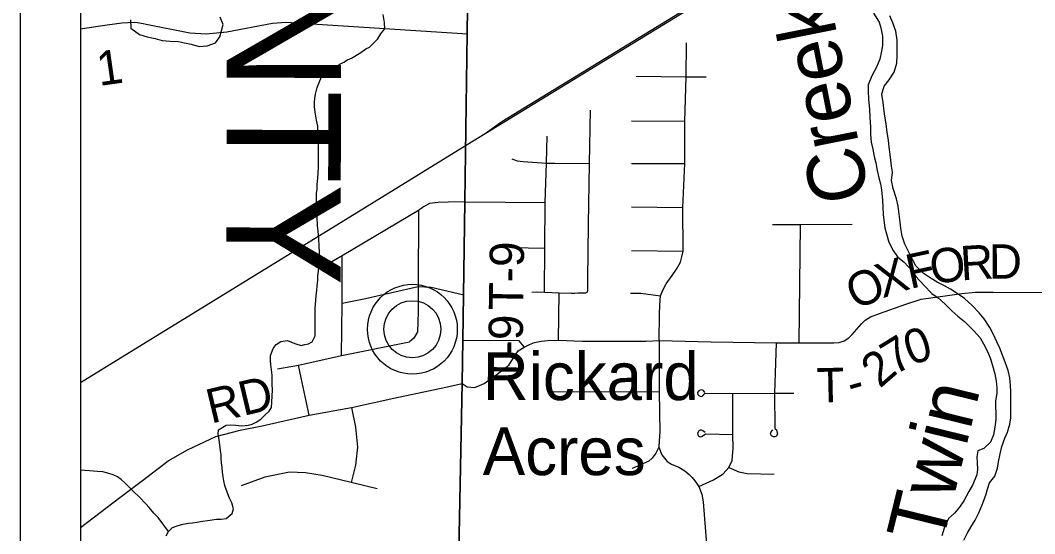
# Model space of a CAD drawing. Extents: x -7.3 to 34, y 0 to 22.
# Drawn here: x 2 to 3.68, y 17.363 to 18.213 of the extents above; entities that cross this region are included whole.
import ezdxf

# ---------------------------------------------------------------- set-up
doc = ezdxf.new("R2010")
doc.units = 0
for name, color, linetype in [('GM_X_Corporation', 7, 'Continuous'), ('GM_X_County_Road', 7, 'Continuous'), ('GM_X_County_Road_Text', 7, 'Continuous'), ('GM_X_County_Text', 7, 'Continuous'), ('GM_X_Major_River', 7, 'Continuous'), ('GM_X_Major_River_Text', 7, 'Continuous'), ('GM_X_Minor_River', 7, 'Continuous'), ('GM_X_Rail_Line', 7, 'Continuous'), ('GM_X_Township_Road', 7, 'Continuous'), ('GM_X_Township_Road_Text', 7, 'Continuous'), ('GM_X_Unincorporated', 7, 'Continuous'), ('GM_X_Unincorporated_Location', 7, 'Continuous'), ('GM_X_Unincorporated_Text', 7, 'Continuous'), ('SH_Data', 7, 'Continuous')]:
    doc.layers.add(name, color=color, linetype=linetype)

msp = doc.modelspace()

# ---------------------------------------------------------------- linework, layer by layer
at = {"layer": 'GM_X_Corporation'}
for points in [[(2.1, 20.0921), (2.1, 14.1)], [(2.1, 20.0921), (2.1, 17.0429)], [(2.7253, 17.2786), (2.7319, 17.6124), (2.7331, 17.6845), (2.7344, 17.7586), (2.7366, 17.9136), (2.7405, 18.1914), (2.7466, 18.6965), (2.7401, 19.6966), (2.7402, 19.7107)], [(2.7402, 19.7107), (2.7401, 19.6966), (2.7466, 18.6965), (2.7405, 18.1914), (2.7366, 17.9136), (2.7344, 17.7586), (2.7331, 17.6845), (2.7319, 17.6124), (2.7253, 17.2786)], [(2.7253, 17.2786), (2.7319, 17.6124), (2.7331, 17.6845), (2.7344, 17.7586), (2.7366, 17.9136), (2.7405, 18.1914), (2.7466, 18.6965), (2.7401, 19.6966), (2.7402, 19.7107)], [(2.7402, 19.7107), (2.7401, 19.6966), (2.7466, 18.6965), (2.7405, 18.1914), (2.7366, 17.9136), (2.7344, 17.7586), (2.7331, 17.6845), (2.7319, 17.6124), (2.7253, 17.2786)]]:
    msp.add_lwpolyline(points, dxfattribs=at)
at = {"layer": 'GM_X_County_Road'}
msp.add_lwpolyline([(2.1, 17.3735), (2.1648, 17.4235), (2.2023, 17.4517), (2.2448, 17.4839), (2.2768, 17.502), (2.324, 17.5245), (2.3644, 17.5348), (2.4007, 17.5419), (2.4787, 17.5598), (2.5485, 17.5723), (2.6188, 17.5877), (2.7048, 17.6058), (2.7321, 17.6118)], dxfattribs=at)
at = {"layer": 'GM_X_Major_River'}
for points in [[(3.4134, 18.2251), (3.4229, 18.2104), (3.4257, 18.2009), (3.4284, 18.1871), (3.4283, 18.1719), (3.4266, 18.1621), (3.4236, 18.1492), (3.4183, 18.1361), (3.4107, 18.1214), (3.4046, 18.1064), (3.4044, 18.0969), (3.4052, 18.0824), (3.4066, 18.0664), (3.4074, 18.0527), (3.4081, 18.0364), (3.4086, 18.0242), (3.4094, 18.0116), (3.4121, 18.0002), (3.4145, 17.9879), (3.4172, 17.9776), (3.4195, 17.9646), (3.4223, 17.9528), (3.4247, 17.9428), (3.4263, 17.9325), (3.4281, 17.9158), (3.429, 17.904), (3.4294, 17.8918), (3.4303, 17.8823), (3.4322, 17.87), (3.4346, 17.8601), (3.4388, 17.8459), (3.446, 17.8321), (3.453, 17.822), (3.4649, 17.8122), (3.4767, 17.7994), (3.4836, 17.7893)], [(3.4653, 17.843), (3.4607, 17.856), (3.4584, 17.8694), (3.4575, 17.8793), (3.456, 17.8926), (3.454, 17.9056), (3.4513, 17.9178), (3.4461, 17.9351), (3.443, 17.9484), (3.4449, 17.9621), (3.4432, 17.972), (3.442, 17.9819), (3.4407, 17.9915), (3.4395, 18.0033), (3.4379, 18.0151), (3.436, 18.0277), (3.4344, 18.0418), (3.4321, 18.0548), (3.4305, 18.0673), (3.4293, 18.0776), (3.427, 18.091), (3.4308, 18.1046), (3.4394, 18.115), (3.4477, 18.1277), (3.4518, 18.1424), (3.4525, 18.155), (3.4524, 18.1652), (3.4524, 18.1804), (3.4502, 18.1953), (3.4452, 18.2095), (3.4406, 18.221)], [(3.5629, 17.3527), (3.5685, 17.3636), (3.5748, 17.3744), (3.5816, 17.386), (3.588, 17.398), (3.5932, 17.4112), (3.5993, 17.4274), (3.6022, 17.4372), (3.6056, 17.4477), (3.6142, 17.4589), (3.6187, 17.4717), (3.6205, 17.4823), (3.6231, 17.4955), (3.6257, 17.5076), (3.631, 17.5215), (3.635, 17.5313), (3.6392, 17.5445), (3.6406, 17.5555), (3.6409, 17.5692), (3.6409, 17.5836), (3.6406, 17.5977), (3.6405, 17.6095), (3.6389, 17.6217), (3.6362, 17.6335), (3.6312, 17.6473), (3.627, 17.6592), (3.6224, 17.6707), (3.6177, 17.6811), (3.6123, 17.6934), (3.6062, 17.7046), (3.5967, 17.7192), (3.5886, 17.7289), (3.5768, 17.741), (3.5638, 17.7527), (3.5534, 17.7598), (3.5407, 17.7681), (3.531, 17.7737), (3.519, 17.7797), (3.5089, 17.786), (3.4955, 17.7947), (3.4833, 17.8068), (3.4779, 17.8172), (3.4729, 17.8276), (3.4653, 17.843)], [(3.4836, 17.7893), (3.4973, 17.7742), (3.5102, 17.7613), (3.5202, 17.7538), (3.5321, 17.7437), (3.5428, 17.7324), (3.5528, 17.7234), (3.564, 17.7147), (3.5787, 17.6999), (3.5898, 17.6875), (3.5956, 17.6775), (3.6021, 17.6651), (3.6064, 17.6544), (3.6102, 17.6421), (3.6144, 17.6283), (3.6164, 17.6161), (3.6176, 17.6051), (3.6177, 17.5956), (3.6152, 17.5835), (3.6153, 17.5732), (3.6158, 17.563), (3.6159, 17.5527), (3.6144, 17.5398), (3.6118, 17.5273), (3.6073, 17.5149), (3.596, 17.5046), (3.5861, 17.5006), (3.5843, 17.4904), (3.5848, 17.4805), (3.5853, 17.4703), (3.5847, 17.4608), (3.5774, 17.4435), (3.571, 17.433), (3.5631, 17.418), (3.556, 17.4072), (3.5477, 17.3975), (3.5376, 17.3883), (3.5304, 17.3725), (3.5267, 17.3597)]]:
    msp.add_lwpolyline(points, dxfattribs=at)
at = {"layer": 'GM_X_Minor_River'}
for points in [[(2.1825, 18.2144), (2.1829, 18.2003), (2.1975, 18.1898), (2.2103, 18.1861), (2.2236, 18.1835), (2.2349, 18.1802), (2.2481, 18.1788), (2.2618, 18.1786), (2.272, 18.1764), (2.2833, 18.1739), (2.2965, 18.1702), (2.3098, 18.1711), (2.3232, 18.1762), (2.3306, 18.1863), (2.3331, 18.1961), (2.336, 18.2063), (2.3313, 18.2186)], [(2.4909, 17.9019), (2.4906, 17.9156), (2.4907, 17.927), (2.4915, 17.9335), (2.4919, 17.9418), (2.4931, 17.952), (2.494, 17.9691), (2.4937, 17.9828), (2.4942, 18.0044), (2.4943, 18.0124), (2.4929, 18.0314), (2.4926, 18.0379), (2.4908, 18.0481), (2.4882, 18.0614), (2.4875, 18.0709), (2.4876, 18.0778), (2.488, 18.0842), (2.4892, 18.091), (2.4919, 18.1024), (2.495, 18.1107), (2.4992, 18.1198), (2.5034, 18.1258), (2.5145, 18.1326), (2.522, 18.1371), (2.5361, 18.1442), (2.5422, 18.1479), (2.5486, 18.1509), (2.5642, 18.1602), (2.5726, 18.1662), (2.5786, 18.1692), (2.5916, 18.1824), (2.5985, 18.1929), (2.6038, 18.1993), (2.6035, 18.2096), (2.6013, 18.2229)], [(2.2419, 17.36), (2.2453, 17.3671), (2.2522, 17.3735), (2.2598, 17.3765), (2.2693, 17.3794), (2.2787, 17.3809), (2.2855, 17.3816), (2.2923, 17.3826), (2.3018, 17.3841), (2.3101, 17.3855), (2.3177, 17.3866), (2.3249, 17.3873), (2.3325, 17.3876), (2.3412, 17.3886), (2.3511, 17.3969), (2.353, 17.4048), (2.3504, 17.4144), (2.3467, 17.422), (2.3437, 17.4296), (2.3411, 17.4368), (2.3389, 17.4433), (2.3371, 17.4509), (2.336, 17.4577), (2.3349, 17.4654), (2.3342, 17.4733), (2.3335, 17.4809), (2.3328, 17.4881), (2.3325, 17.4946), (2.3318, 17.5007), (2.3307, 17.5106), (2.3293, 17.5189), (2.3278, 17.5284), (2.3286, 17.5352), (2.3408, 17.5431), (2.3484, 17.5438), (2.357, 17.5433), (2.3669, 17.5421), (2.3775, 17.5431), (2.3843, 17.5446), (2.3907, 17.548), (2.3983, 17.5528), (2.4056, 17.56), (2.412, 17.566), (2.4159, 17.5724), (2.4167, 17.5811), (2.4176, 17.6016), (2.4173, 17.6111), (2.4173, 17.6191), (2.417, 17.6259), (2.4149, 17.6438), (2.4142, 17.6498), (2.4142, 17.6586), (2.4188, 17.6703), (2.4238, 17.6767), (2.4318, 17.6816), (2.4424, 17.6834), (2.4492, 17.6803), (2.4567, 17.6775), (2.465, 17.6752), (2.4715, 17.6766), (2.4775, 17.6777), (2.4836, 17.6811), (2.4882, 17.6909), (2.4883, 17.6996), (2.4887, 17.7061), (2.4884, 17.7175), (2.4885, 17.7365), (2.489, 17.7433), (2.4894, 17.7494), (2.4902, 17.7577), (2.491, 17.766), (2.4918, 17.774), (2.4926, 17.7831), (2.4931, 17.7899), (2.4939, 17.7979), (2.4947, 17.8043), (2.4955, 17.8172), (2.4956, 17.8302), (2.4953, 17.8396), (2.4943, 17.8518), (2.4936, 17.8643), (2.4925, 17.8735), (2.4915, 17.8871), (2.4909, 17.9019)], [(2.2453, 17.3671), (2.2285, 17.3901), (2.221, 17.3973), (2.2135, 17.4069), (2.2082, 17.413), (2.1974, 17.4237), (2.188, 17.4329), (2.1801, 17.4406), (2.1733, 17.4475), (2.1669, 17.4529), (2.1609, 17.4575), (2.1541, 17.4606), (2.1466, 17.4633), (2.1368, 17.4657), (2.1277, 17.4665), (2.1145, 17.4674), (2.1065, 17.4678), (2.1001, 17.4683), (2.1, 17.4683)]]:
    msp.add_lwpolyline(points, dxfattribs=at)
at = {"layer": 'GM_X_Rail_Line'}
for points in [[(2.7405, 18.0079), (3.3109, 18.3572), (4.0313, 18.798), (4.702, 19.2088), (4.7774, 19.2546), (4.9109, 19.336), (5.2623, 19.5511), (5.5045, 19.6986), (5.5533, 19.7292), (5.593, 19.7558), (5.6212, 19.7759), (5.6461, 19.795), (5.6821, 19.8246), (5.7051, 19.845), (5.7282, 19.867), (5.7473, 19.8866), (5.7663, 19.9054), (5.7919, 19.9343), (5.8126, 19.9584), (5.8283, 19.9791), (5.855, 20.0143)], [(2.7702, 18.0262), (2.7976, 18.0458), (3.3096, 18.3593), (4.03, 18.8001), (4.7007, 19.211), (4.7761, 19.2568), (4.8865, 19.324), (4.9045, 19.332)], [(2.1, 17.6137), (2.1729, 17.6588), (2.5458, 17.8883), (2.7405, 18.0079)]]:
    msp.add_lwpolyline(points, dxfattribs=at)
at = {"layer": 'GM_X_Township_Road'}
for p, q in [((2.7407, 18.1909), (2.7469, 18.6959)), ((2.7382, 18.0088), (2.7407, 18.1909)), ((3.1008, 18.046), (3.0125, 18.0462)), ((2.7368, 17.913), (2.738, 18.0012)), ((2.738, 18.0012), (2.7382, 18.0088)), ((3.0122, 17.9761), (3.1008, 17.9764)), ((2.7346, 17.7581), (2.7368, 17.913)), ((2.7368, 17.913), (2.8694, 17.9116)), ((3.0122, 17.9045), (3.0977, 17.9034)), ((3.2903, 17.6793), (3.2925, 17.8747)), ((2.8139, 17.8372), (2.8689, 17.8363)), ((3.0126, 17.8323), (3.0982, 17.8314)), ((2.8913, 17.6836), (2.8927, 17.7621)), ((2.7333, 17.6839), (2.7346, 17.7581)), ((2.7321, 17.6118), (2.7333, 17.6839)), ((2.8781, 17.5986), (3.0585, 17.5981)), ((3.2495, 17.5963), (3.2813, 17.5958))]:
    msp.add_line(p, q, dxfattribs=at)
for points in [[(2.1, 18.1996), (2.1103, 18.2011), (2.1441, 18.206), (2.1683, 18.2091), (2.1891, 18.2104), (2.194, 18.2096), (2.2038, 18.208)], [(2.2038, 18.208), (2.2087, 18.2072), (2.2811, 18.1927), (2.3078, 18.1908), (2.3419, 18.1944), (2.4177, 18.2089), (2.4404, 18.2106), (2.7407, 18.1909)], [(3.0583, 17.683), (3.0589, 17.7262), (3.0592, 17.7425), (3.0604, 17.757), (3.0641, 17.7664), (3.0701, 17.7769), (3.0798, 17.791), (3.0872, 17.8015), (3.0934, 17.8128), (3.0956, 17.8218), (3.0982, 17.8314), (3.0977, 17.9034), (3.1008, 17.9764), (3.1008, 18.046), (3.103, 18.1197), (3.1034, 18.1762)], [(3.0202, 18.1211), (3.103, 18.1197), (3.1362, 18.12)], [(2.8474, 17.7634), (2.855, 17.7636), (2.8683, 17.7634), (2.8927, 17.7621), (2.9123, 17.7619), (2.9187, 17.7619), (2.9238, 17.7621), (2.9294, 17.762), (2.9342, 17.7621), (2.9366, 17.7623), (2.9379, 17.7625), (2.9391, 17.7632), (2.9395, 17.764), (2.9398, 17.7649), (2.9399, 17.766), (2.9399, 17.7685), (2.9399, 17.7851), (2.9414, 17.8761), (2.9428, 17.9765), (2.9446, 18.0649)], [(2.8683, 17.7634), (2.8689, 17.8363), (2.8694, 17.9116), (2.8716, 17.9771), (2.8725, 18.0214)], [(2.8141, 17.9841), (2.8231, 17.9807), (2.833, 17.9798), (2.8716, 17.9771), (2.8855, 17.9767), (2.9428, 17.9765)], [(2.7368, 17.913), (2.7085, 17.9121), (2.6922, 17.9115), (2.678, 17.9102), (2.6681, 17.9044), (2.6596, 17.8983), (2.5329, 17.8235), (2.4948, 17.8016)], [(2.6596, 17.8983), (2.6593, 17.7719), (2.6589, 17.7546), (2.659, 17.7307), (2.658, 17.6977), (2.6518, 17.6872), (2.6449, 17.6809)], [(3.3782, 17.8752), (3.2925, 17.8747), (3.2462, 17.8749)], [(2.5322, 17.6583), (2.5329, 17.7448), (2.5329, 17.8235)], [(2.7346, 17.7581), (2.6806, 17.771), (2.6593, 17.7719), (2.5721, 17.7523), (2.5329, 17.7448)], [(2.7321, 17.6118), (2.74, 17.6066), (2.7532, 17.6055), (2.7686, 17.612), (2.7898, 17.6275), (2.8091, 17.6423), (2.8247, 17.6662), (2.8346, 17.6723), (2.8435, 17.6767), (2.8515, 17.6799), (2.8628, 17.6823), (2.8741, 17.6831), (2.8913, 17.6836), (2.9305, 17.6824), (3.037, 17.6821), (3.0583, 17.683), (3.1442, 17.6813), (3.2518, 17.6793), (3.2903, 17.6793), (3.3478, 17.6795), (3.3567, 17.6801), (3.3648, 17.6825), (3.3722, 17.6877), (3.3782, 17.6932), (3.3933, 17.7109), (3.3997, 17.7168), (3.4085, 17.7225), (3.4235, 17.7278), (3.4671, 17.7433), (3.4922, 17.7515), (3.5596, 17.7611), (3.5823, 17.7634), (3.6117, 17.7634), (3.6952, 17.763)], [(3.0107, 17.7618), (3.0279, 17.7616), (3.0604, 17.757)], [(2.4259, 17.6362), (2.4607, 17.6424), (2.5322, 17.6583), (2.6449, 17.6809)], [(2.7333, 17.6839), (2.8251, 17.6834), (2.8346, 17.6723)], [(3.0583, 17.683), (3.0585, 17.5981), (3.0592, 17.5322), (3.0582, 17.517)], [(3.2518, 17.6793), (3.2495, 17.5963), (3.2499, 17.5377), (3.2525, 17.5355), (3.2529, 17.5326), (3.2541, 17.5287), (3.2527, 17.5251), (3.2501, 17.524), (3.2475, 17.524), (3.2444, 17.5253), (3.2429, 17.5286), (3.2438, 17.5319), (3.2463, 17.5355)], [(2.4787, 17.5598), (2.4653, 17.6212), (2.4607, 17.6424)], [(3.1341, 17.5974), (3.1317, 17.6004), (3.1289, 17.6018), (3.1261, 17.6012), (3.1237, 17.5997), (3.122, 17.5973), (3.1222, 17.594), (3.1247, 17.5915), (3.1277, 17.5904), (3.1306, 17.5917), (3.1327, 17.5943), (3.1343, 17.5963), (3.1805, 17.5954), (3.2495, 17.5963)], [(3.1239, 17.4418), (3.1483, 17.4525), (3.1643, 17.4625), (3.1737, 17.4728), (3.1791, 17.4846), (3.1811, 17.5049), (3.1805, 17.5274), (3.1805, 17.5954)], [(2.5485, 17.5723), (2.555, 17.54), (2.5584, 17.5069), (2.5554, 17.4769), (2.548, 17.448)], [(3.1346, 17.5307), (3.1306, 17.5339), (3.1284, 17.5348), (3.126, 17.5347), (3.1239, 17.5335), (3.123, 17.5315), (3.122, 17.5297), (3.1223, 17.5277), (3.1227, 17.5257), (3.1243, 17.5243), (3.1271, 17.5238), (3.1293, 17.5247), (3.1314, 17.5257), (3.1353, 17.5288), (3.1805, 17.5274)], [(3.0582, 17.517), (3.0575, 17.5069), (3.0529, 17.4967), (3.0466, 17.4884), (3.0411, 17.4832), (3.0134, 17.4716)], [(3.0575, 17.5069), (3.0627, 17.4938), (3.0713, 17.4831), (3.0786, 17.4786), (3.0908, 17.4737), (3.1009, 17.4673), (3.108, 17.4615), (3.1132, 17.4566), (3.1176, 17.4509), (3.1239, 17.4418), (3.1287, 17.4286), (3.1314, 17.4159), (3.1385, 17.325), (3.1387, 17.2946)], [(2.5911, 17.4374), (2.548, 17.448), (2.5002, 17.4595), (2.4722, 17.4643), (2.4459, 17.465), (2.4052, 17.4569), (2.3661, 17.4427)], [(3.1737, 17.4728), (3.1902, 17.466), (3.2041, 17.4631), (3.249, 17.462)]]:
    msp.add_lwpolyline(points, dxfattribs=at)
at = {"layer": 'GM_X_Unincorporated'}
for radius in [0.0744, 0.0472]:
    msp.add_circle((2.6495, 17.7019), radius, dxfattribs=at)
at = {"layer": 'GM_X_Unincorporated_Location'}
msp.add_line((2.6495, 17.7019), (2.6495, 17.7019), dxfattribs=at)
at = {"layer": 'SH_Data'}
for p, q in [((2, 21), (2, 14)), ((2.1, 20.9), (2.1, 14.1))]:
    msp.add_line(p, q, dxfattribs=at)

# ---------------------------------------------------------------- texts
at = {"layer": 'GM_X_County_Road_Text'}
msp.add_text('RD', height=0.05682, rotation=13.4401, dxfattribs=at).set_placement((2.316, 17.5454))
at = {"layer": 'GM_X_County_Text'}
msp.add_text('BUTLER COUNTY', height=0.189394, rotation=269.9014, dxfattribs=at).set_placement((2.3449, 19.913))
at = {"layer": 'GM_X_Major_River_Text'}
for s, height, rotation, p in [('Creek', 0.09478, 101.3066, (3.4072, 17.9206)), ('Twin', 0.09475, 76.2282, (3.5265, 17.342))]:
    msp.add_text(s, height=height, rotation=rotation, dxfattribs=at).set_placement(p)
at = {"layer": 'GM_X_Township_Road_Text'}
for s, height, rotation, p in [('1', 0.0568, 8.1297, (2.1309, 18.1046)), ('T-9', 0.05682, 89.0397, (2.8328, 17.7327)), ('F', 0.0568, 12.2278, (3.4739, 17.7685)), ('O', 0.0568, 7.3419, (3.5101, 17.7764)), ('R', 0.0568, 3.4602, (3.5587, 17.7827)), ('D', 0.0568, 0.306, (3.6045, 17.7855)), ('X', 0.0568, 18.5887, (3.4281, 17.753)), ('O', 0.0568, 23.8989, (3.3837, 17.7332)), ('T-9', 0.05682, 89.0447, (2.8311, 17.6117)), ('0', 0.0568, 18.3049, (3.4748, 17.6414)), ('7', 0.0568, 31.5461, (3.4481, 17.6245)), ('2', 0.0568, 40.8927, (3.4237, 17.603)), ('T', 0.0568, 1.2687, (3.3195, 17.5806)), ('-', 0.0568, 15.9059, (3.3776, 17.5839))]:
    msp.add_text(s, height=height, rotation=rotation, dxfattribs=at).set_placement(p)
at = {"layer": 'GM_X_Unincorporated_Text'}
for s, p in [('Rickard', (2.7659, 17.5846)), ('Acres', (2.7659, 17.4604))]:
    msp.add_text(s, height=0.07898, rotation=0, dxfattribs=at).set_placement(p)

doc.saveas('drawing.dxf')
